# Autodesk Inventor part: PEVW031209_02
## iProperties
Created: 2009-12
Part Number: PEVW031209_02
Cost Center: 0 kg
Material: 1.0037 St 37-2
Document SubType Name: Modellieren
Designer: Student_TAB
Authority: 0 mm^3
Density: 7.85 g/cm^3
Author: Student_TAB
SaveDate: 2007-07-03
SaveTime: 10:26
TotalMass: 0 kg
TotalVolume: 0 mm^3
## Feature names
1. Umdrehung1 [Revolution]
2. Extrusion1
3. Extrusion2
4. Extrusion3
5. Extrusion4
6. Extrusion5
7. Extrusion6
8. Runde Anordnung2 [Circular Pattern]
